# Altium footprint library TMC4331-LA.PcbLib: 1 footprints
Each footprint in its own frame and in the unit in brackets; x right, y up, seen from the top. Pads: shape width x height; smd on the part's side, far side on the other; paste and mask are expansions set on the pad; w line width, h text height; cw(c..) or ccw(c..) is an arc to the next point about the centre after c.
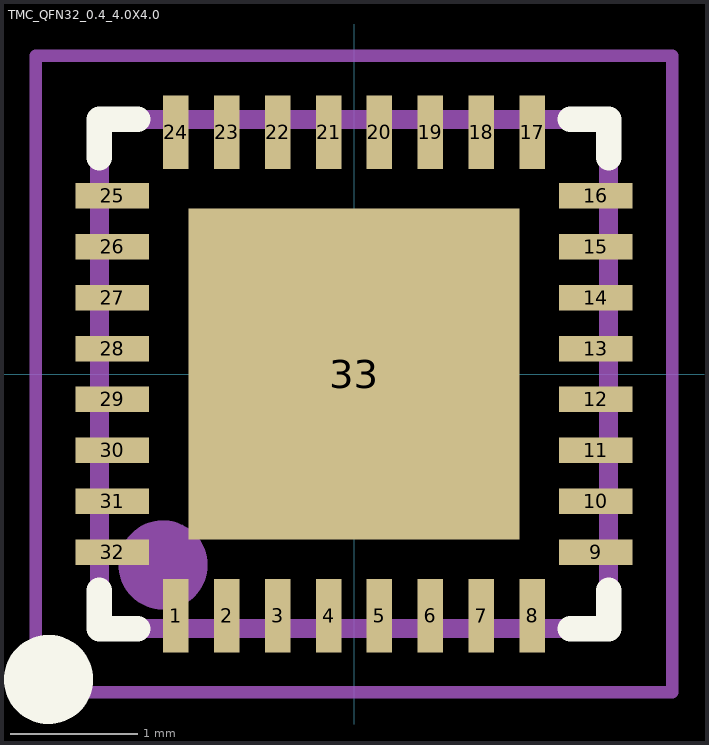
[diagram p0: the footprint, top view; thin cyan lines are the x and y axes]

## TMC_QFN32_0.4_4.0X4.0 [mm]
pads (33):
  rect 0.2x0.58 smd: 1(-1.4,-1.9) 2(-1,-1.9) 3(-0.6,-1.9) 4(-0.2,-1.9) 5(0.2,-1.9) 6(0.6,-1.9) 7(1,-1.9) 8(1.4,-1.9) 17(1.4,1.9) 18(1,1.9) 19(0.6,1.9) 20(0.2,1.9) 21(-0.2,1.9) 22(-0.6,1.9) 23(-1,1.9) 24(-1.4,1.9)
  rect 0.58x0.2 smd: 9(1.9,-1.4) 10(1.9,-1) 11(1.9,-0.6) 12(1.9,-0.2) 13(1.9,0.2) 14(1.9,0.6) 15(1.9,1) 16(1.9,1.4) 25(-1.9,1.4) 26(-1.9,1) 27(-1.9,0.6) 28(-1.9,0.2) 29(-1.9,-0.2) 30(-1.9,-0.6) 31(-1.9,-1) 32(-1.9,-1.4)
  rrect0% 2.6x2.6 smd paste-25.4: 33(0,0)
L26-Silk Screen Top (Multiple PADS layers...):
  circle w0.5: c-2.4,-2.4 r0.1
  lines w0.2: -2,-1.7 -2,-2 -1.7,-2 ; -2,1.7 -2,2 -1.7,2 ; 1.7,-2 2,-2 2,-1.7 ; 1.7,2 2,2 2,1.7
L23-Paste Mask Top (Multiple PADS layers...):
  region: 0.2,-0.2 1.2,-0.2 1.2,-1.2 0.2,-1.2
  region: 0.2,1.2 1.2,1.2 1.2,0.2 0.2,0.2
  region: -1.2,1.2 -0.2,1.2 -0.2,0.2 -1.2,0.2
  region: -1.2,-0.2 -0.2,-0.2 -0.2,-1.2 -1.2,-1.2
L13:
  circle w0.5: c-1.5,-1.5 r0.1
  lines w0.15: -2,-2 -2,2 2,2 2,-2 -2,-2
L15 (Multiple PADS layers...):
  lines w0.1: -2.5,-2.5 -2.5,2.5 2.5,2.5 2.5,-2.5 -2.5,-2.5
